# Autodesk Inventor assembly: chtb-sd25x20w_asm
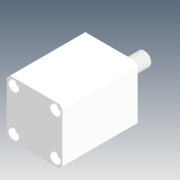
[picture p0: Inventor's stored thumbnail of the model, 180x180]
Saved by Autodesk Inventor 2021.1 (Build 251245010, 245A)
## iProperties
Company: Microsoft
Created: 2018-05
Part Number: chtb-sd25x20w_asm
Description: STEP AP214
Document SubType Name: Assembly
Designer: user
Title: chtb-sd25x20w_asm.STEP
Author: Windows
Revision Number: ÈÎºÎ
Sending System: SolidWorks 2015
Preprocessor: SwSTEP 2.0
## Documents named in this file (4)
- D:\Vault_2016\Projekty\Clamptek\Hydraulic\CHTB\CHTB-25\Inventor\chtb-sd25x20w\chtb-sd25x20w_asm.iam
- D:\Vault_2016\Projekty\Clamptek\Hydraulic\CHTB\CHTB-25\Inventor\chtb-sd25x20w\CHTB-25QG.ipt
- D:\Vault_2016\Projekty\Clamptek\Hydraulic\CHTB\CHTB-25\Inventor\chtb-sd25x20w\CHTB-SD25X20NBT.ipt
- D:\Vault_2016\Projekty\Clamptek\Hydraulic\CHTB\CHTB-25\Inventor\chtb-sd25x20w\CHTB-SD25X20WHSG.ipt
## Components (3 placed, 3 different names)
1. CHTB-25QG_1
2. CHTB-SD25X20NBT_2
3. CHTB-SD25X20WHSG_3
